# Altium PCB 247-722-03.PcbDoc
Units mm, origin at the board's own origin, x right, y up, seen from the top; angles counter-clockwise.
Board outline 143.8 x 64 mm, 4 copper layers (Top Layer, Int1_T, Int2-B, Bottom (GND)), stack 1.57 mm thick; 113 components, 68 nets, 298 pads, 352 vias.
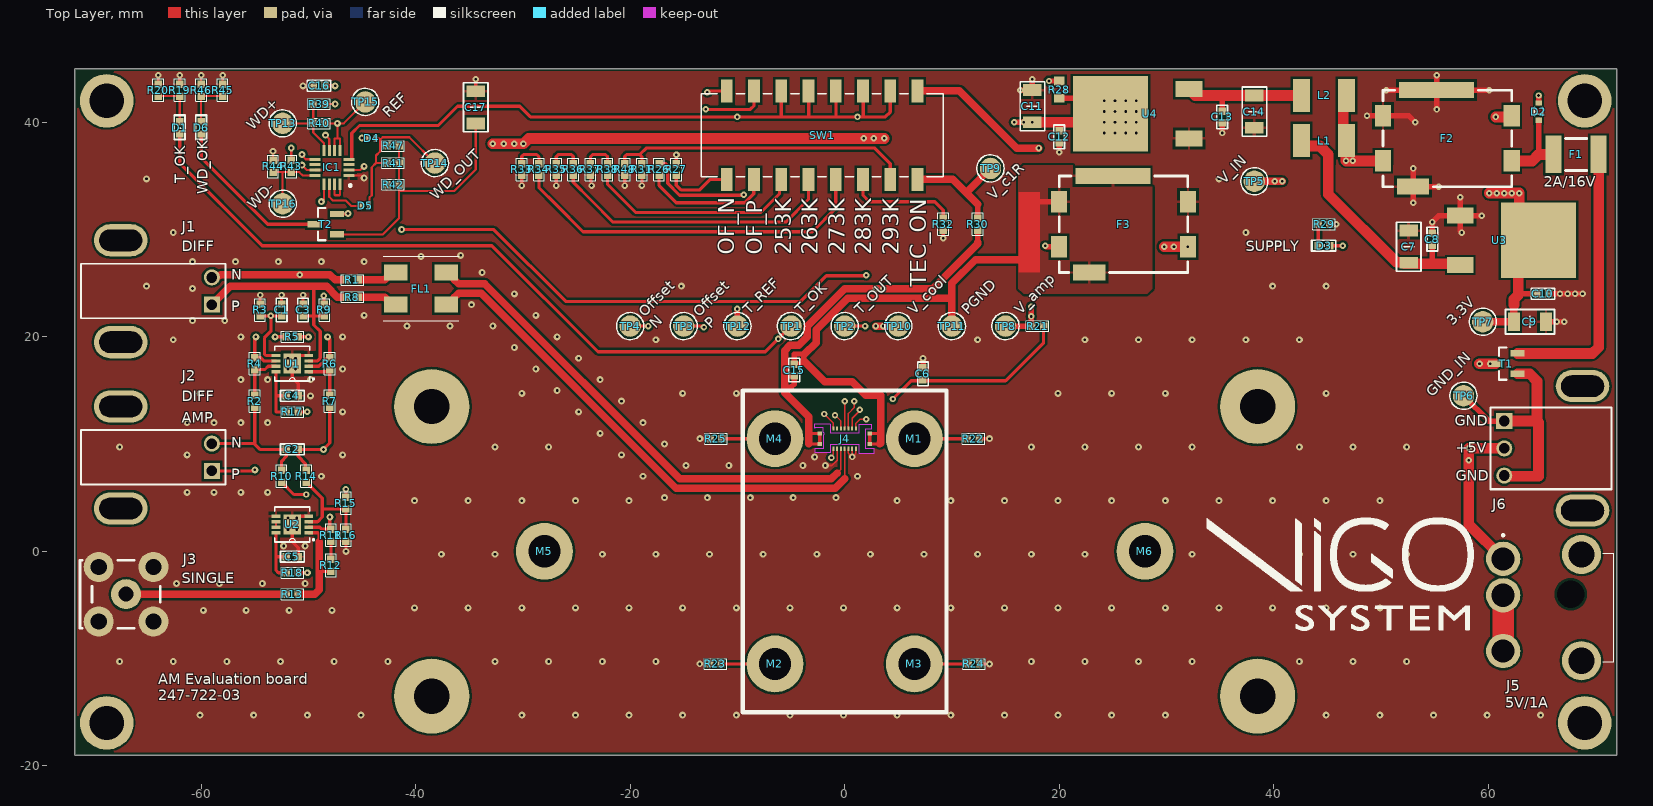
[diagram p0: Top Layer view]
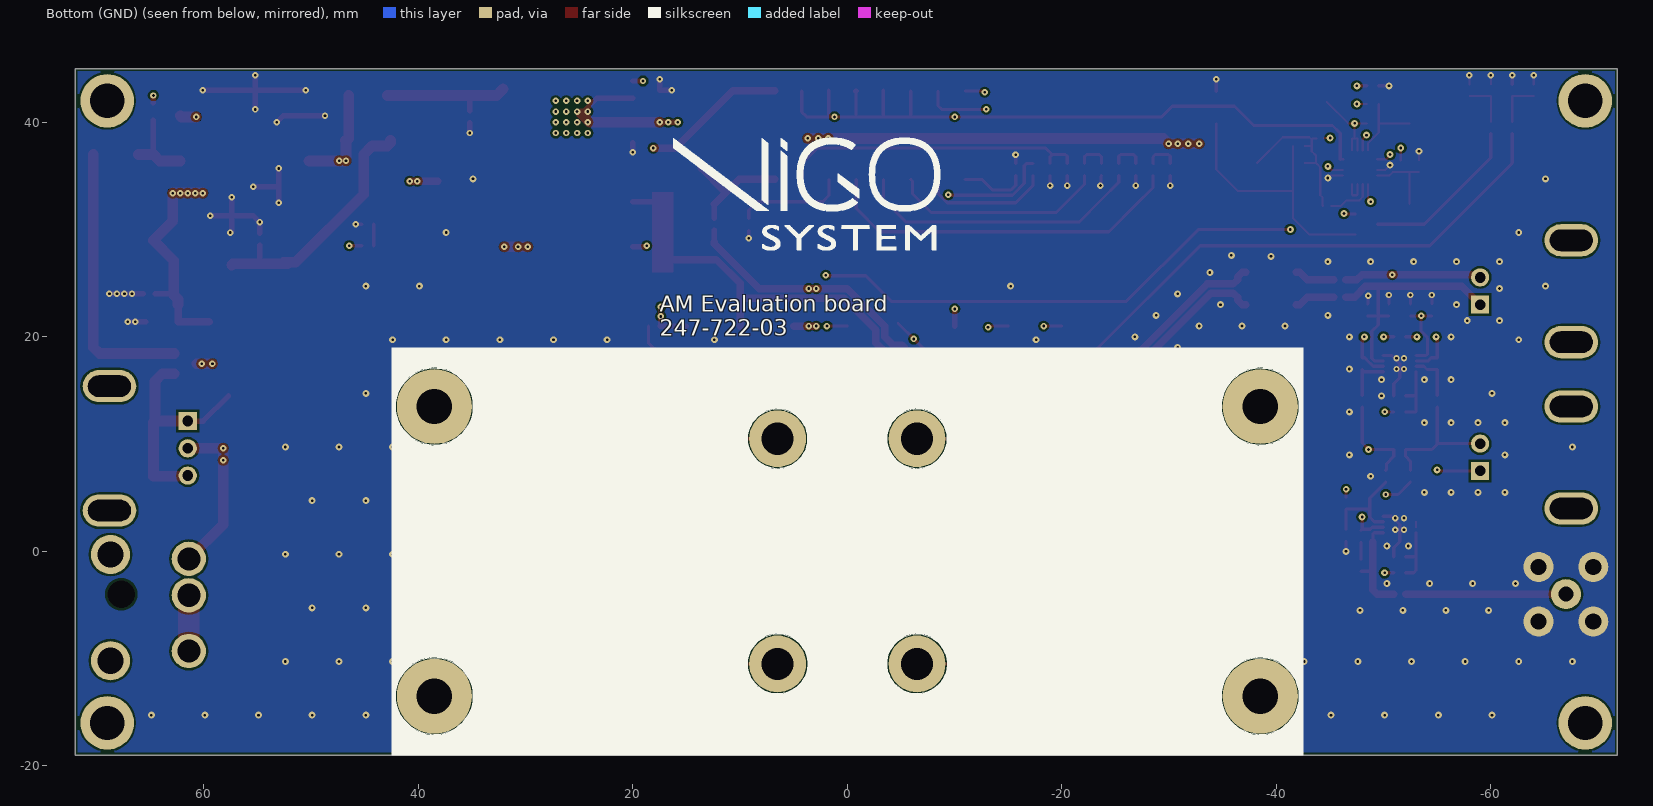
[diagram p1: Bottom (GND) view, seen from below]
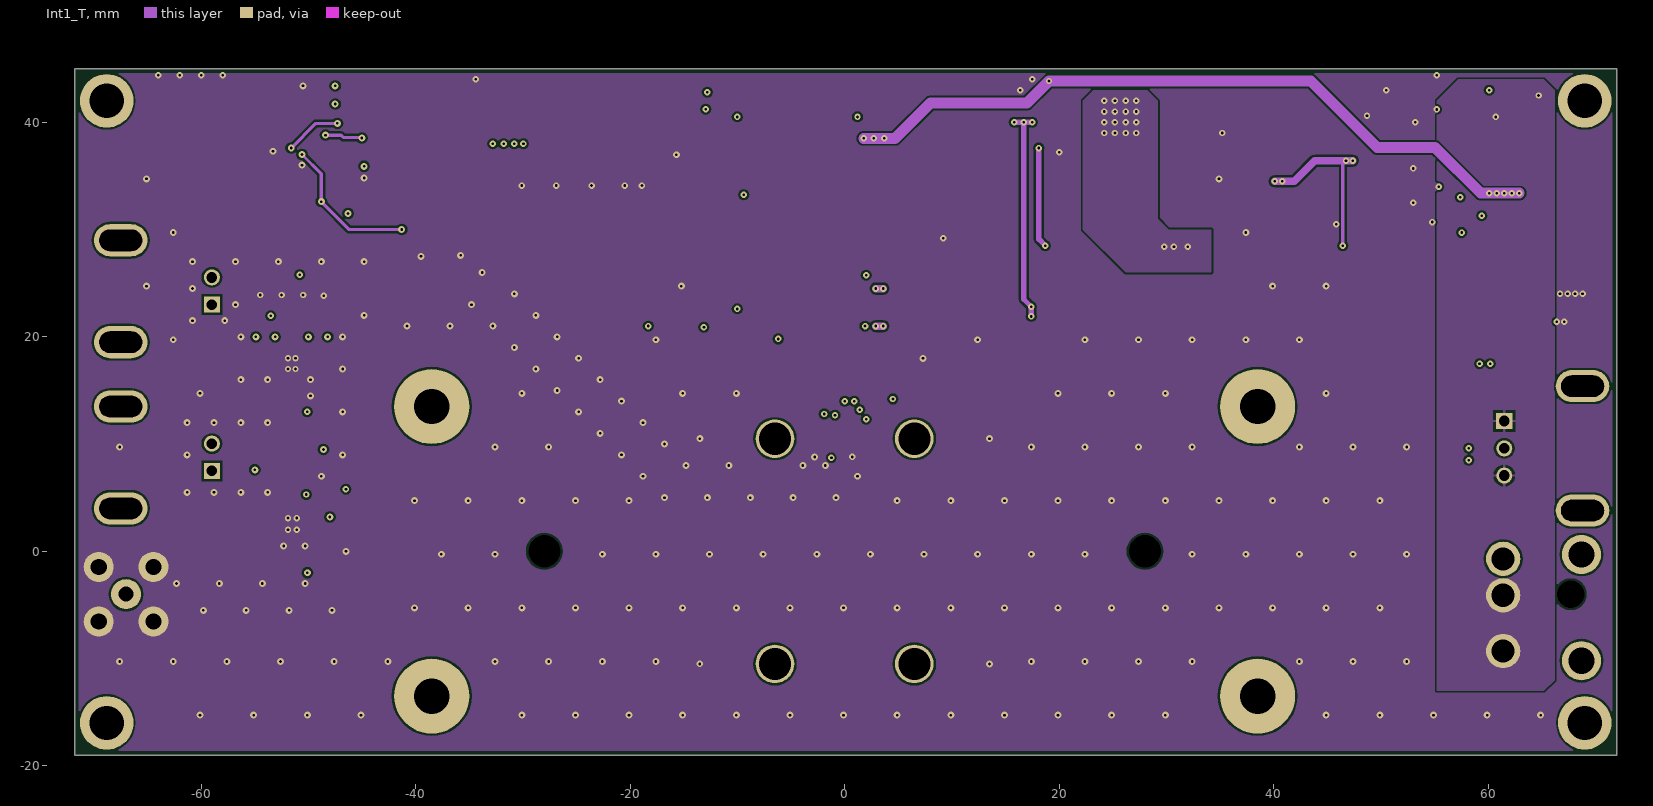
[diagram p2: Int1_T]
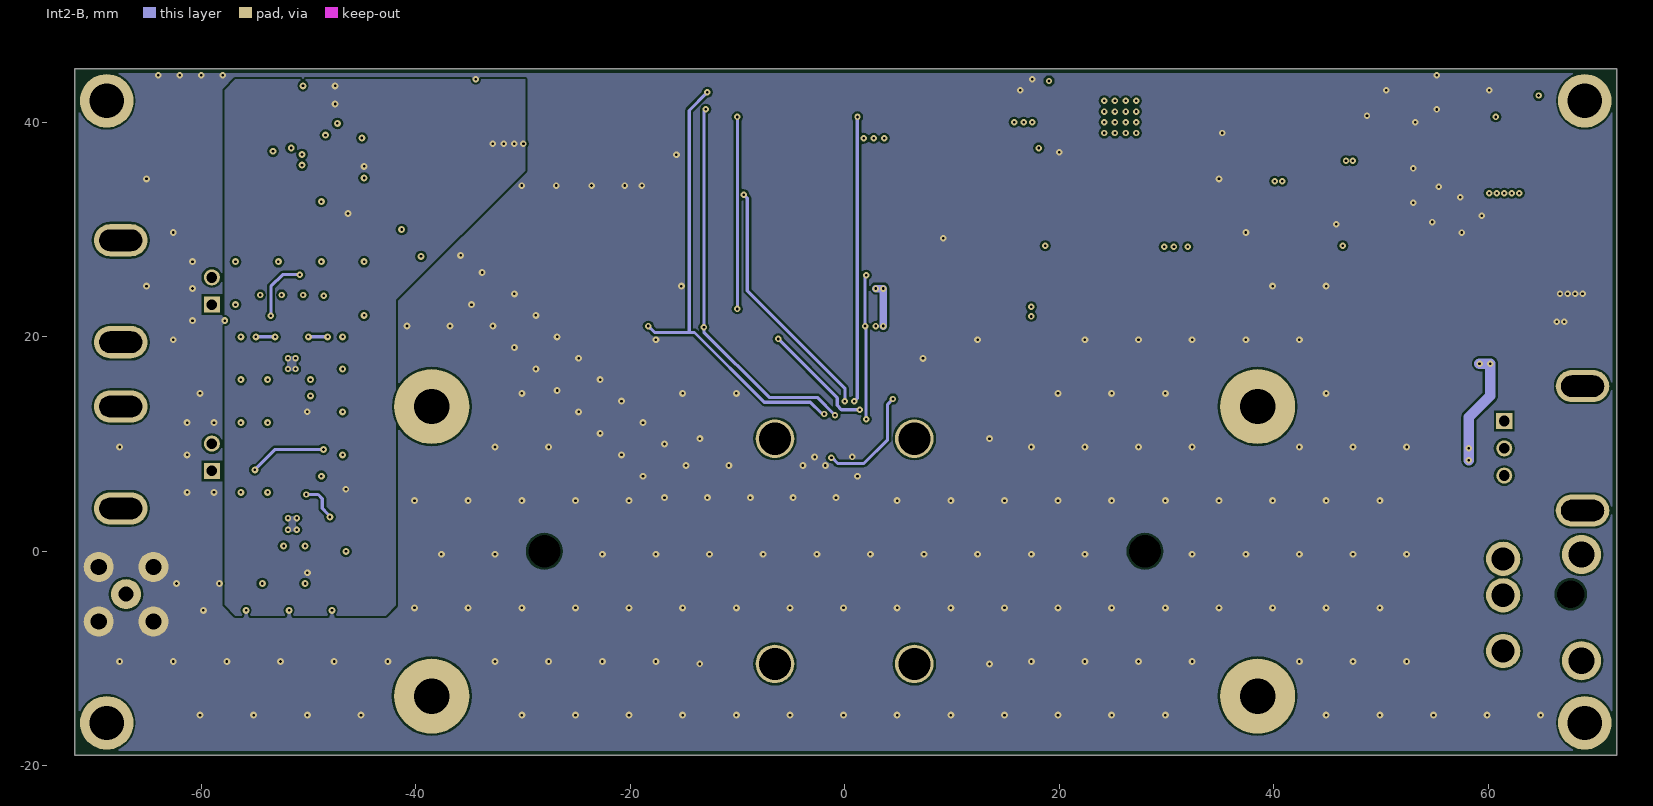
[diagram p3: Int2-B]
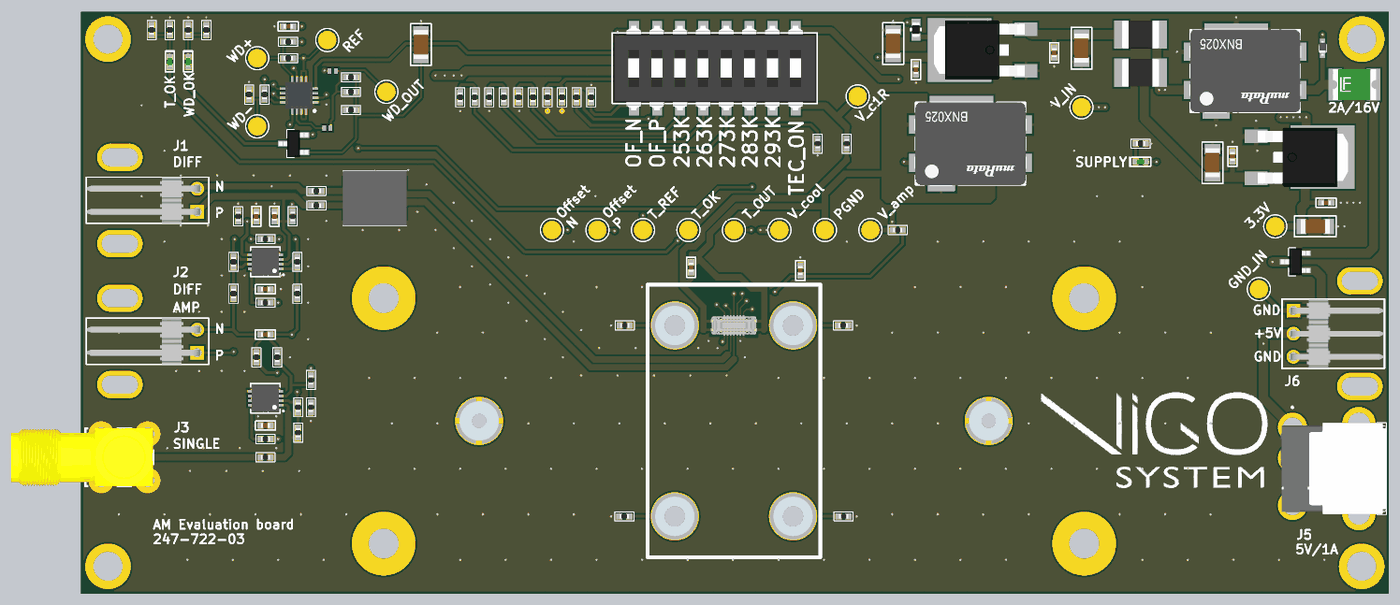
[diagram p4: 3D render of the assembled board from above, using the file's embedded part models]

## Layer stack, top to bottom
Top Solder: solder mask 0.025, SM-001, Dk 4
Top Layer: signal copper 0.035
Dielectric 1: core 0.36, Core-009, Dk 4.5
Int1_T: signal copper 0.035
Dielectric 6: prepreg 0.71, PP-006, Dk 4.1
Int2-B: signal copper 0.035
Dielectric 11: core 0.36, Core-009, Dk 4.5
Bottom (GND): signal copper 0.035
Bottom Solder: solder mask 0.025, SM-001, Dk 4

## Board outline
-71.8,-19 -71.8,45 72,45 72,-19

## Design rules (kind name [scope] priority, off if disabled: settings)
BoardOutlineClearance "BoardOutlineClearance inner layers" [(not IsKeepOut) and onMid] p1: gap=0.4 ignorepadtopadclearanceinfootprint=FALSE
BoardOutlineClearance "BoardOutlineClearance_1 outer layers" [(not IsKeepOut) and OnOutside] p2: gap=0.25 ignorepadtopadclearanceinfootprint=FALSE
Clearance Clearance_poly_50Ohm [InNetClass('50ohm')] p1: gap=0.3 ignorepadtopadclearanceinfootprint=FALSE except(0: Arc-Hole Track-Hole SMDPad-Hole THPad-Hole Via-Hole Fill-Hole Poly-Hole Region-Hole Text-Hole)
Clearance [not IsKeepOut vs not IsKeepOut] p2: gap=0.15 ignorepadtopadclearanceinfootprint=FALSE except(0: Arc-Hole Track-Hole SMDPad-Hole THPad-Hole Via-Hole Fill-Hole Poly-Hole Region-Hole Text-Hole; 0.2: Arc-Poly Track-Poly SMDPad-Poly THPad-Poly Via-Poly Fill-Poly Poly-Poly)
Clearance Clearance_keepout [All] p3: gap=0.001 ignorepadtopadclearanceinfootprint=FALSE except(0: Arc-Hole Track-Hole SMDPad-Hole THPad-Hole Via-Hole Fill-Hole Poly-Hole Region-Hole Text-Hole)
ComponentClearance [All] p1: gap=0.25 collisioncheckmode=3 verticalgap=0.2 showdistances=FALSE
DiffPairsRouting [All] p1: maxlimit=0.15 minlimit=0.15 mostfreqgap=0.15 toplayer_minwidth=0.15 toplayer_maxwidth=0.7 toplayer_prefwidth=0.15 midlayer1_minwidth=0.15 midlayer1_maxwidth=0.7 midlayer1_prefwidth=0.15 midlayer4_minwidth=0.15 midlayer4_maxwidth=0.7 midlayer4_prefwidth=0.15 bottomlayer_minwidth=0.15 bottomlayer_maxwidth=0.7 bottomlayer_prefwidth=0.15 maxuncoupledlength=12.5
Height [All] p1: minheight=0 maxheight=25 prefheight=12.5
HoleSize HoleSize-PTH [All] p1: absolutevalues=TRUE maxlimit=4 minlimit=0.25 maxpercent=80.000 minpercent=20.000
HoleToHoleClearance [All] p1: gap=0.35 allowstackedmicrovias=TRUE
MatchedLengths "Schematic Matched Net Lengths_1" [InNet('OUT_P')] p1: tolerance=2 checknetsindiffpair=TRUE checkdiffpairvsdiffpair=FALSE checkxsignals=FALSE checkothers=FALSE
MatchedLengths "Schematic Matched Net Lengths" [InNet('OUT_N')] p2: tolerance=2 checknetsindiffpair=TRUE checkdiffpairvsdiffpair=FALSE checkxsignals=FALSE checkothers=FALSE
MaxMinImpedance "Schematic Impedance Constraint_7" [InNet('OUTF_P')] p1: minimum=47,00 maximum=53,00
MaxMinImpedance "Schematic Impedance Constraint_6" [InNet('OUTF_N')] p2: minimum=47,00 maximum=53,00
MaxMinImpedance "Schematic Impedance Constraint_3" [InNet('NetR12_2')] p3: minimum=47,00 maximum=53,00
MaxMinImpedance "Schematic Impedance Constraint_2" [InNet('NetJ3_1')] p4: minimum=47,00 maximum=53,00
MinimumAnnularRing AR [All] p1: minimumring=0.174
MinimumSolderMaskSliver [All] p1: minsoldermaskwidth=0.08
PlaneClearance PlaneClearance-IPI [All] p1: clearance=0.25
PolygonConnect PolygonConnect-via [IsVia] p1: connectstyle=Direct reliefconductorwidth=0.254 reliefentries=4 polygonreliefangle="45 Angle" airgapwidth=0.254
PolygonConnect PolygonConnect-xTW_1_bottom [All vs OnLayer('Bottom Layer')] p2: connectstyle=Direct reliefconductorwidth=0.254 reliefentries=4 polygonreliefangle="90 Angle" airgapwidth=0.254
PolygonConnect PolygonConnect-xTW_1_bottom_1 [(PadIsPlated = 'False')] p3: connectstyle=Relief reliefconductorwidth=0.2 reliefentries=4 polygonreliefangle="90 Angle" airgapwidth=0.2
PolygonConnect PolygonConnect-big [AsMM(HoleDiameter) > 1] p4: connectstyle=Direct reliefconductorwidth=0.254 reliefentries=4 polygonreliefangle="90 Angle" airgapwidth=0.254
PolygonConnect PolygonConnect-xTW_1 [All] p5: connectstyle=Relief reliefconductorwidth=0.254 reliefentries=4 polygonreliefangle="90 Angle" airgapwidth=0.254
RoutingCorners [All] p1: cornerstyle=45-Degree minsetback=2.5 maxsetback=2.5
RoutingVias "RoutingVias > 0.45mm" [(ObjectKind = 'Via')] p1: holewidth=0.25 width=0.7 viastyle="Through Hole" minholewidth=0.25 minwidth=0.6 maxholewidth=0.9 maxwidth=1.25 // finishet hole size > 0.45mm
SilkToSilkClearance [All] p1: silktosilkclearance=0.2
SilkToSolderMaskClearance SilkscreenOverComponentPads [IsPad] p1: minsilkscreentomaskgap=0.04 clearancetoexposedcopper=TRUE
SolderMaskExpansion [All] p1: expansion=0
Width Width-xTW [not IsKeepOut] p1: maxlimit=2 minlimit=0.15 preferedwidth=0.7
20 further rules are at their usual default settings.

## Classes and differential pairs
component class "Window comparator": C16 C17 D4 D5 D6 IC1 R39 R40 R41 R42 R43 R44 R45 R46 R47 T2 TP13 TP14 TP15 TP16
component class TEMPERATURE: R31 R32 R33 R34 R35 R36 R37 R38 R48 TP12
component class SUP_MAIN: C7 C8 C9 C10 C11 C12 C13 C14 C15 D2 D3 F1 F2 F3 J5 J6 L1 L2 R28 R29 R30 T1 TP5 TP6 TP7 TP8 TP9 TP10 TP11 U3 U4
component class SUP_AMP: C4 C5 R17 R18
component class OFFSET: R26 R27 SW1 TP3 TP4
component class AMP: C1 C2 C3 J1 J2 J3 R1 R2 R3 R4 R5 R6 R7 R8 R9 R10 R11 R12 R13 R14 R15 R16 U1 U2
component class "247-722-03 Main": C6 D1 FL1 J4 M1 M2 M3 M4 M5 M6 R19 R20 R21 R22 R23 R24 R25 TP1 TP2
differential pair OUTF: +OUTF_P -OUTF_N
differential pair OUT: +OUT_P -OUT_N

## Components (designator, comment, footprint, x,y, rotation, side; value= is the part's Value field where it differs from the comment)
C1 "10p" 0402_CAP -52.5,22.5 r90 top
C2 "NC" 0402_CAP -51.5,9.5 r0 top
C3 "10p" 0402_CAP -50.5,22.5 r90 top
C4 "100n/35V" 0402_CAP -51.5,14.5 r0 top
C5 "100n/35V" 0402_CAP -51.5,-0.5 r0 top
C6 "100n/35V" 0402_CAP 7.3,16.55 r90 top
C7 "22u/25V" 1206_CAP_H 52.6,28.4 r270 top
C8 "100n/35V" 0402_CAP 54.8,29.1 r90 top
C9 "22u/25V" 1206_CAP_H 63.9,21.4 r180 top
C10 "100n/35V" 0402_CAP 65.1,24 r0 top
C11 "22u/25V" 1206_CAP_H 17.5,41.5 r270 top
C12 "100n/35V" 0402_CAP 20,38.65 r270 top
C13 "100n/35V" 0402_CAP 35.2,40.5 r270 top
C14 "22u/25V" 1206_CAP_H 38.2,41 r90 top
C15 "100n/35V" 0402_CAP -4.7,16.9 r90 top
C16 "100n/35V" 0402_CAP -49,43.4 r180 top
C17 "22u/25V" 1206_CAP_H -34.4,41.4 r270 top
D1 "T_OK" 0402_LED_G -62,39.5 r90 top value=KPG-1005VGC-TT
D2 "ESDA12-1K" SOD523 64.7,41 r270 top
D3 "SUPPLY" 0402_LED_G 44.7,28.5 r180 top value=KPG-1005VGC-TT
D4 "1PS10SB82" DFN-1006-2 -44.1,38.5 r0 top
D5 "1PS10SB82" DFN-1006-2 -44.7,32.2 r0 top
D6 "WD_OK" 0402_LED_G -60,39.5 r90 top value=KPG-1005VGC-TT
F1 "2.6A/16V" 1812_FUSE 68.2,37 r180 top
F2 "BNX025H01L" BNX025 57.2,38.5 r180 top
F3 "BNX025H01L" BNX025 27,30.5 r180 top
FL1 "PA4339.132NLT" PA4339132NLT -39.5,24.5 r0 top
IC1 "TSX564IQ4T" QFN16 -47.8,35.8 r180 top
J1 "10129379-902004BLF" HDR_100mil_1x2M_RA -59,24.27 r90 top
J2 "10129379-902004BLF" HDR_100mil_1x2M_RA -59,8.77 r90 top
J3 "3-1478978-1" "SMA_ 3-1478978-1" -67,-4 r180 top
J4 "101R014FB110" 101R014FB110 0,10.5 r0 top locked
J5 "2.5x5.5mm" PJ079BH 61.4,-0.7 r180 top value=PJ079BH
J6 "68016-403HLF" HDR_100mil_1x3M_RA 61.5,12.14 r270 top
L1 "56R@10MHz 10A" 1612_EMI 44.7,38.3 r180 top
L2 "56R@10MHz 10A" 1612_EMI 44.7,42.5 r180 top
M1 "9774010943R" TP_THT_1500_3000 6.5,10.5 r180 top locked
M2 "9774010943R" TP_THT_1500_3000 -6.5,-10.5 r180 top locked
M3 "9774010943R" TP_THT_1500_3000 6.5,-10.5 r180 top locked
M4 "9774010943R" TP_THT_1500_3000 -6.5,10.5 r180 top locked
M5 "9774025243R" 9774025243 -28,0 r0 top
M6 "9774025243R" 9774025243 28,0 r0 top
R1 "0R" 0402_RES -45.9,25.3 r0 top
R2 "0R" 0402_RES -55,14 r90 top
R3 "49R9" 0402_RES -54.5,22.5 r90 top
R4 "100R" 0402_RES -55,17.5 r90 top
R5 "49R9" 0402_RES -51.5,20 r0 top
R6 "100R" 0402_RES -48,17.5 r270 top
R7 "0R" 0402_RES -48,14 r90 top
R8 "0R" 0402_RES -45.9,23.7 r0 top
R9 "49R9" 0402_RES -48.5,22.5 r90 top
R10 "49R9" 0402_RES -52.5,7 r90 top
R11 "100R" 0402_RES -47.9,1.5 r90 top
R12 "100R" 0402_RES -47.9,-1.3 r90 top
R13 "49R9" 0402_RES -51.5,-4 r0 top
R14 "49R9" 0402_RES -50.2,7 r90 top
R15 "2.2k" 0402_RES -46.5,4.5 r90 top
R16 "220R" 0402_RES -46.5,1.5 r270 top
R17 "10R" 0402_RES -51.5,13 r180 top
R18 "10R" 0402_RES -51.5,-2 r180 top
R19 "2k" 0402_RES -62,43 r90 top
R20 "2k" 0402_RES -64,43 r90 top
R21 "0R" 0402_RES 18,21 r0 top
R22 "0R" 0402_RES 12,10.5 r0 top
R23 "0R" 0402_RES -12.05,-10.5 r180 top
R24 "0R" 0402_RES 12.05,-10.5 r0 top
R25 "0R" 0402_RES -12,10.5 r180 top
R26 "0R" 0402_RES -17.3,35.6 r270 top
R27 "0R" 0402_RES -15.7,35.6 r270 top
R28 "NC" 0603_RES 20,43.05 r270 top
R29 "2k" 0402_RES 44.7,30.5 r180 top
R30 "100m" 0402_RES 12.4,30.5 r90 top
R31 "4k7" 0402_RES -18.9,35.6 r270 top
R32 "4k7" 0402_RES 9.2,30.5 r270 top
R33 "390R" 0402_RES -30.1,35.6 r270 top
R34 "7k5" 0402_RES -28.5,35.6 r90 top
R35 "4k7" 0402_RES -26.9,35.6 r270 top
R36 "10k" 0402_RES -25.3,35.6 r90 top
R37 "2k" 0402_RES -23.7,35.6 r270 top
R38 "33k" 0402_RES -22.1,35.6 r90 top
R39 "10k" 0402_RES -49,41.7 r180 top
R40 "22R" 0402_RES -49,39.9 r0 top
R41 "2k" 0402_RES -42.1,36.2 r0 top
R42 "33k" 0402_RES -42.1,34.2 r0 top
R43 "22R" 0402_RES -51.6,35.9 r270 top
R44 "10k" 0402_RES -53.3,35.9 r270 top
R45 "2k" 0402_RES -58,43 r270 top
R46 "2k" 0402_RES -60,43 r270 top
R47 "2k" 0402_RES -42.1,37.8 r0 top
R48 "7k5" 0402_RES -20.5,35.6 r270 top
SW1 "A6SN-8104-P" SW_A6SN-8101_OMR -2.1,38.8 r90 top
T1 "Si2319CDS" SOT23-GSD 61.7,17.5 r180 top
T2 "Si2319CDS" SOT23-GSD -48.4,30.5 r180 top
TP1 "T_OK" TP_2 -5,21 r180 top
TP2 "=Value" TP_2 0,21 r270 top
TP3 "OffsetP" TP_2 -15,21 r0 top
TP4 "OffsetN" TP_2 -20,21 r90 top
TP5 "V_in" TP_2 38.2,34.5 r180 top
TP6 "Value" TP_2 57.7,14.5 r180 top
TP7 "3.3V" TP_2 59.5,21.4 r180 top
TP8 "V_amp" TP_2 15,21 r180 top
TP9 "V_c1R" TP_2 13.6,35.7 r180 top
TP10 "V_cool" TP_2 5,21 r180 top
TP11 "Value" TP_2 10,21 r180 top
TP12 "T_REF" TP_2 -10,21 r270 top
TP13 "WD+" TP_2 -52.4,39.9 r270 top
TP14 "WD_OUT" TP_2 -38.2,36.2 r270 top
TP15 "REF" TP_2 -44.7,41.9 r270 top
TP16 "WD-" TP_2 -52.4,32.4 r270 top
U1 "ADA4896-2ACPZ" LFCSP-8 -51.5,17.5 r180 top
U2 "ADA4896-2ACPZ" LFCSP-8 -51.5,2.5 r180 top
U3 "3V3" TO252 62.3,29 r0 top value=AZ1084CD-3.3TRG1
U4 "3V3" TO252 27.2,40.8 r180 top value=AZ1084CD-3.3TRG1

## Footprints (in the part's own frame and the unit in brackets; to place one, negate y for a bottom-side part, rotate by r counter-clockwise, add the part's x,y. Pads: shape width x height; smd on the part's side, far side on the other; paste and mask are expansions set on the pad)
101R014FB110 [mm] "14pins + 2 power paths"
  rect 0.18x0.4 smd: 1(-1.05,-0.95) 2(-1.05,0.95) 3(-0.7,-0.95) 4(-0.7,0.95) 5(-0.35,-0.95) 6(-0.35,0.95) 7(0,-0.95) 8(0,0.95) 9(0.35,-0.95) 10(0.35,0.95) 11(0.7,-0.95) 12(0.7,0.95) 13(1.05,-0.95) 14(1.05,0.95)
  rect 0.4x0.385 smd: MP1(-2.33,-0.483) MP2(-2.33,0.483) MP3(2.33,-0.483) MP4(2.33,0.483)
  body extent -2.45,-0.99 2.45,1.01, height 0.78
0402_CAP [mm]
  rect 0.7x0.7 smd paste-0.03: 1(0.55,0) 2(-0.55,0)
  silkscreen extent -1.1,-0.5 1.1,0.5, body extent -0.5,-0.25 0.5,0.25, height 0.5
0402_LED_G [mm]
  rect 0.7x0.7 smd paste-0.03 mask+0.03: 1(-0.55,0) 2(0.55,0)
  silkscreen extent -1.1,-0.5 1.2,0.5, body extent -0.5,-0.25 0.51,0.25, height 0.45
0402_RES [mm]
  rect 0.7x0.7 smd paste-0.03: 1(0.55,0) 2(-0.55,0)
  silkscreen extent -1.05,-0.5 1.05,0.5, body extent -0.5,-0.25 0.5,0.25, height 0.3
0603_RES [mm]
  rect 0.8x1 smd: 1(-0.8,0) 2(0.8,0)
  silkscreen extent -0.1,-0.55 0.1,0.55, body extent -0.81,-0.41 0.81,0.41, height 0.81
1206_CAP_H [mm]
  rect 1.1x1.7 smd: 1(-1.499,0) 2(1.499,0)
  silkscreen extent -2.29,-1.14 2.29,1.14, body extent -1.6,-0.8 1.6,0.8, height 1.6
1612_EMI [mm] "3216(metric)"
  rect 1.6x3.1 smd: 1(-2.1,0) 2(2.1,0)
  body extent -2.03,-1.52 2.03,1.53, height 2.28
1812_FUSE [mm]
  rect 1.5x3.5 smd: 1(-2.1,0) 2(2.1,0)
  silkscreen extent -1,-1.5 1,1.5, body extent -2.37,-1.71 2.36,1.7, height 1.34
9774025243 [mm] "SMT Steel Spacer with internal Thread M2, height 2.5mm"
  round 5.3 / inner round 0 / far side round 0 hole 3 unplated: 1(0,0)
  body extent -2.17,-2.17 2.18,2.17, height 2.5
BNX025 [mm] "Murata filter"
  rect 1.5x2 smd: 1(-5,2.1) 2(7,2.1) 3(-5,-2.1) 4(7,-2.1)
  rect 7x1.5 smd: 4(2,-4.5)
  rect 3x1.5 smd: 4(4.2,4.5)
  silkscreen extent -5,-4.5 7,4.5, body extent -5.15,-4.65 7.15,4.65, height 3.5
DFN-1006-2 [mm]
  rect 0.4x0.6 smd: 1(-0.35,0) 2(0.35,0)
HDR_100mil_1x2M_RA [mm]
  rect 1.5x1.5 / inner rect 1.5x1.5 / far side rect 1.7x1.7 hole 1: 1(-1.27,0)
  round 1.5 / inner round 1.5 / far side round 1.7 hole 1: 2(1.27,0)
  silkscreen extent -2.54,-1.27 2.54,12.2, body extent -2.54,-0.3 2.54,12.16, height 2.42
HDR_100mil_1x3M_RA [mm] "Connector; Header; 3 Position"
  rect 1.5x1.5 / inner rect 1.5x1.5 / far side rect 1.7x1.7 hole 1: 1(0,0)
  round 1.5 / inner round 1.5 / far side round 1.7 hole 1: 2(2.54,0) 3(5.08,0)
  silkscreen extent -1.27,-1.27 6.35,10, body extent -1.26,-0.33 6.36,9.87, height 2.42
LFCSP-8 [mil]
  rect 32x12 smd mask+1.97: 1(-60,30) 2(-60,10) 3(-60,-10) 4(-60,-30) 5(60,-30) 6(60,-10) 7(60,10) 8(60,30)
  rect 63x74 smd mask+1.97: 9(0,0)
  silkscreen extent -79,-64 64,64, body extent -59,-59 59,59, height 31
PA4339132NLT [mm]
  rect 2.2x1.5 smd: 1(-2.35,1.5) 2(-2.35,-1.5) 3(2.35,-1.5) 4(2.35,1.5)
  silkscreen extent -3.5,-3 3.5,3, body extent -3.5,-3 3.5,3, height 3.9
PJ079BH [mm]
  round 3.2 hole 2.154: 1(0,0) 2(0,8.6) 3(0,3.4)
  round 3.653 hole 2.435: MH1(-7.3,9.5) MH2(-7.3,-0.4)
  round 1.3 hole 2.6 unplated: MH3(-6.3,3.3)
  silkscreen extent -10.3,-2.3 0.1,9.6, body extent -10.32,-0.49 1.33,9.58, height 7.29
QFN16 [mm]
  rect 1.05x0.28 smd paste-0.025 mask+0.04: 1(-1.575,0.75) 2(-1.575,0.25) 3(-1.575,-0.25) 4(-1.575,-0.75) 9(1.575,-0.75) 10(1.575,-0.25) 11(1.575,0.25) 12(1.575,0.75)
  rect 0.28x1.05 smd paste-0.025 mask+0.04: 5(-0.75,-1.575) 6(-0.25,-1.575) 7(0.25,-1.575) 8(0.75,-1.575) 13(0.75,1.575) 14(0.25,1.575) 15(-0.25,1.575) 16(-0.75,1.575)
  silkscreen extent -1.8,1.6 -1.6,1.8, body extent -1.52,-1.52 1.52,1.52, height 0.9
"SMA_ 3-1478978-1" [mm]
  round 2.8 hole 1.4: 1(0,0)
  round 2.8 hole 1.5: 2(-2.55,2.55) 2(-2.55,-2.55) 2(2.55,2.55) 2(2.55,-2.55)
  silkscreen extent -3.17,-3.17 4.3,3.18, body extent -3.13,-3.17 12.42,3.18, height 10.11
SOD523 [mm]
  rect 0.5x0.6 smd: 1(-0.8,0) 2(0.8,0)
  silkscreen extent -0.38,-0.38 0.38,0.38, body extent -0.8,-0.4 0.8,0.4, height 0.7
SOT23-GSD [mm]
  rect 1.3x0.6 smd: 1(-1.05,0.95) 2(1.05,0) 3(-1.05,-0.95)
  silkscreen extent 0,-1.5 0.7,1.5, body extent -1.6,-1.5 1.6,1.5, height 1.1
SW_A6SN-8101_OMR [mm]
  rect 2.15x1.1 smd paste+0 mask+0: 1(-4.125,8.89) 2(-4.125,6.35) 3(-4.125,3.81) 4(-4.125,1.27) 5(-4.125,-1.27) 6(-4.125,-3.81) 7(-4.125,-6.35) 8(-4.125,-8.89) 9(4.125,-8.89) 10(4.125,-6.35) 11(4.125,-3.81) 12(4.125,-1.27) 13(4.125,1.27) 14(4.125,3.81) 15(4.125,6.35) 16(4.125,8.89)
  silkscreen extent -3.88,-11.28 3.88,11.28, body extent -4.65,-11.15 4.65,11.15, height 4.56
TO252 [mm] "D-PAK, 3-Pads, Body 5,8x6,7mm (max), IPC Low Density"
  rect 2.5x1.5 smd: 1(-4.9,2.3) 3(-4.9,-2.3)
  rect 7x7 smd: 2(2.4,0)
  body extent -4.74,-3.25 5.2,3.25, height 2.2
TP_2 [mm] "Test Point"
  round 2 smd paste-1: 1(0,0)
  silkscreen extent -1.27,-1.27 1.27,1.27
TP_THT_1500_3000 [mm]
  round 5.3 / inner round 3.6 / far side round 5.3 hole 3: 1(0,0)
  body extent -2.17,-2.17 2.18,2.17, height 1.01

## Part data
C1 C3: library part cap_0402_10p, "Ceramic capacitor", Supplier Part Number 1=CL05C100CB5NNNC
C2: library part cap_0402_4p7_50V, "Ceramic capacitor", Supplier Part Number 1=CL05C4R7BB5NNNC
C4 C5 C6 C8 C10 C12 C13 C15 C16: library part cap_0402_100n_35V, "Ceramic capacitor", Manufacturer="Taiyo Yuden", Supplier Part Number 1=2113067
C7 C9 C11 C14 C17: library part cap_1206_22u_25V, "Ceramic capacitor", Supplier Part Number 1=1797010
D1 D3 D6: library part d_LED_0402_G, Manufacturer=Kinbright, Supplier Part Number 1=KPG-1005CGC-TT
D2: library part d_TVS_ESDA12-1K, Manufacturer="Diodes Incorporated"
D4 D5: library part d_1PS10SB82, "Schottky barrier diode, low capacitance (1pF)", Manufacturer=Nexperia
F1: library part f_PTC_1812_2A6_16V, Supplier Part Number 1=650-MINISMDC260F/162
F2 F3: library part fil_BNX025H01L, Manufacturer=Murata
FL1: library part b_PA4339.132NLT, "Filter", Manufacturer=Pulse, Mouser Part Number=673-PA4339.132NLT
IC1: library part ic_TSX564IQ4T, "quad rail-to-rail precision opamp", Manufacturer=ST, Supplier Part Number 1=497-13695-1-ND
J1 J2: library part j_HDR_100mil_1x2_RA, "Header, 2-Pin", Manufacturer=Amphenol, Supplier Part Number 1=649-1012937990204BLF
J3: library part j_SMA_3-1478978-1, Manufacturer="TE Connectivity"
J4: library part j_101R014FB110, "14pin + 2 power paths, 0.35mm pitch", Manufacturer="Amphenol ICC", Manufacturer_Name="Amphenol ICC / Aorora", Supplier Part Number 1=3577436
J5: library part j_PJ-079BH, "Connector", Arrow Part Number=PJ-079BH, Manufacturer="CUI Devices", Manufacturer_Name="CUI Inc.", Mouser Part Number=490-PJ-079BH
J6: library part j_HDR_100mil_1x3_RA, "Header, 3-Pin", Manufacturer=Amphenol, Supplier Part Number 1=649-68016-403HLF
L1 L2: library part l_1612_EMI_56R_10A, "DO5040H-103", Supplier Part Number 1=875-DM1612X560R-10
M1 M2 M3 M4: library part m_spacer_1mm_fi2.25_WA-SMST_9774010943, Manufacturer="Wurth Elektronik", Supplier Part Number 1=732-10938-1-ND
M5 M6: library part m_spacer_2.5mm_fi2.25_WA_SMT_9774025243, "WA-SMSI SMT Steel Spacer, internal Thread, OD 4.35mm, M2x2.5mm", Manufacturer="Wurth Elektronik", Manufacturer Part Number=9774025243, Operating Temperature="-55 to +150degC"
R1 R2 R7 R8 R21 R22 R23 R24 R25 R26 R27: library part res_0402_0R, "Resistior", Supplier Part Number 1=SMD0402-0R
R3 R5 R9 R10 R13 R14: library part res_49R9/0.1%/TF, "Resistior", Manufacturer=Yageo
R4 R6 R11 R12: library part res_0402_100R/0.1%/TF, "Resistior", Manufacturer=Yageo, Supplier Part Number 1=YAG2301CT-ND
R15: library part res_0402_2.2k/0.1%/TF, "Resistior", Manufacturer=Yageo, Supplier Part Number 1=YAG1402CT-ND
R16: library part res_0402_220R/0.1%/TF, "Resistior", Manufacturer=Yageo, Supplier Part Number 1=YAG4207CT-ND
R17 R18: library part res_0402_10R, "Resistior", Supplier Part Number 1=SMD0402-10R-1%
R19 R20 R29 R37 R41 R45 R46 R47: library part res_0402_2k, "Resistior", Supplier Part Number 1=SMD0402-2k-1%
R28: library part res_0603_NC, "Resistior"
R30: library part res_0402_0R10, "Resistior", Manufacturer=YAGEO, Supplier Part Number 1=603-RL0402FR070R1L
R31 R32 R35: library part res_0402_4k7, "Resistior", Supplier Part Number 1=SMD0402-4k7-1%
R33: library part res_0402_390R, "Resistior", Supplier Part Number 1=SMD0402-390R-1%
R34 R48: library part res_0402_7k5, "Resistior", Supplier Part Number 1=SMD0402-7k5-1%
R36 R39 R44: library part res_0402_10k, "Resistior", Supplier Part Number 1=SMD0402-10K
R38 R42: library part res_0402_33k, "Resistior", Supplier Part Number 1=SMD0402-33k-1%
R40 R43: library part res_0402_22R, "Resistior", Supplier Part Number 1=SMD0402-22R-1%
SW1: library part s_DIP_8_S, "No Description Available", Manufacturer=Omron, Manufacturer_Part_Number=A6SN-8101, Supplier Part Number 1=653-A6SN-8104-P
T1 T2: library part t_Si2319CDS, Manufacturer=Vishay, Supplier Part Number 1=SI2319CDS-T1-GE3
TP1 TP2 TP3 TP4 TP5 TP6 TP7 TP8 TP9 TP10 TP11 TP12 TP13 TP14 TP15 TP16: library part m_TP_2, "Test Point"
U1 U2: library part ic_ADA4896-2, "opamp", Manufacturer="Analog Devices"
U3 U4: library part ic_AZ1084CD-3.3TRG1, "3-TERMINAL  LDO", Manufacturer="DIODES Incorporated", Supplier Part Number 1=AZ1084CD-3.3TRG1DITR-ND

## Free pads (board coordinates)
  round 7 hole 3.3: 49(-38.5,-13.5) 49(-38.5,13.5) 49(38.5,-13.5) 49(38.5,13.5)
  oval 5x3 hole 2 slot 4 at 0 deg: 50(-67.5,29) 50(68.8,15.4) 51(-67.5,19.5) 51(68.8,3.8) 52(-67.5,13.5) 53(-67.5,4)
  round 5 hole 3.2: 54(-68.8,42) 55(-68.8,-16) 56(69,-16) 57(69,42)

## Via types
v1: diameter 0.65, hole 0.25, Top Layer to Bottom (GND), tented both sides, 225 vias
v2: diameter 0.6, hole 0.25, Top Layer to Bottom (GND), tented both sides, 125 vias
v3: diameter 0.6, hole 0.25, Top Layer to Bottom (GND), 2 vias

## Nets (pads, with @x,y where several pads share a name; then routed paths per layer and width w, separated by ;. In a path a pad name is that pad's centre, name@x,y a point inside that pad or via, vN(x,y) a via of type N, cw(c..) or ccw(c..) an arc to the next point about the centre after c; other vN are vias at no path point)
3V3: C9.2 C10.2 C16.2 IC1.2 R15.1 R17.2 R18.2 R28.1 R39.2 T2.3 TP7.1 U3.2 | length 133.7
  Top Layer w0.2: R39.2 v1(-47.5,41.7) ; v1@-46.35,31.45 v1(-46.3,31.5) ; IC1.2 -45.15,35.55 v1(-44.8,35.9)
  Top Layer w0.3: R18.2 -50,-2 v1(-50.1,-2) ; R17.2 v2(-50.1,13) ; C16.2 v1(-47.5,43.4) ; T2.3 v1@-46.35,31.45 ; R15.1 v2(-46.5,5.8)
  Top Layer w0.5: v2(19.05,43.85) R28.1 ; 62.8,23.9 62.9,24 C10.2
  Top Layer w0.7: TP7.1 C9.2 62.4,21.401 62.4,23
  Top Layer w1: v2(-32.8,38) v2(-31.8,38) v2(-30.8,38) v2(-29.95,38) -29.45,38.5 v2(1.778,38.5) v2(2.7,38.5) v2(3.7,38.5) ; v2(60.1,33.4) v2(60.8,33.4) v2(61.5,33.4) v2(62.2,33.4) v2(62.9,33.4) 62.9,30.8 U3.2 62.8,27.1 62.8,23.9 62.4,23.5 62.4,23
  Int1_T w1: v2(1.778,38.5) v2(2.7,38.5) v2(3.7,38.5) 4.7,38.5 8,41.8 17,41.8 v2(19.05,43.85) 43.45,43.85 49.65,37.65 55.05,37.65 59.3,33.4 v2(60.1,33.4) v2(60.8,33.4) v2(61.5,33.4) v2(62.2,33.4) v2(62.9,33.4)
GND: C1.1 C3.1 C4.1 C5.1 C6.1 C7.1 C8.1 C9.1 C10.1 C11.1 C12.1 C13.1 C14.1 C16.1 C17.1 F2.4 F3.3 IC1.1 IC1.11 J3.2 J4.3 J4.9 J4.11 J4.13 R3.1 R9.1 R16.1 R19.1 R20.1 R22.1 R23.1 R24.1 R25.1 R27.2 R29.2 R31.1 R32.1 R33.1 R35.1 R37.1 R42.2 R44.2 R45.2 R46.2 R48.1 U1.4 U1.9 U2.4 U2.5 U2.9 U3.1 U4.1 | length 81.3
  Top Layer w0.15: v1(-1.8,8) -1.2,8 -0.7,8.5 J4.3 ; J4.9 0.35,9.15 v2(0.7,8.8) ; J4.11 v2(0.7,8.8) ; J4.13 1.05,9.15 v2(0.7,8.8)
  Top Layer w0.2: R20.1 v2(-64,44.4) ; R46.2 v2(-60,44.4) ; R45.2 v2(-58,44.4) ; R44.2 v1(-53.3,37.3) ; v1(-50.6,36) -50.15,35.55 IC1.11 ; IC1.1 -45.05,35.05 v1(-44.8,34.8)
  Top Layer w0.3: R19.1 v2(-62,44.4) ; R3.1 v2(-54.5,23.9) ; C1.1 v2(-52.5,23.9) ; C5.1 -50.95,0.35 -51.5,0.9 U2.9 -50.738,3.262 U2.4 ; C4.1 -50.95,15.629 -51.5,16.179 U1.9 -50.738,18.262 U1.4 ; C3.1 v2(-50.5,23.9) ; v1(-50.5,43.4) C16.1 ; v2(-48.566,23.834) -48.533,23.801 -48.533,23.083 R9.1 ; v1(-46.5,0) R16.1 ; C17.1 v2(-34.4,44) ; v2(-30.1,34.1) R33.1 ; v2(-26.9,34.1) R35.1 ; R37.1 -23.65,35 -23.65,34.15 v2(-23.6,34.1) ; v3(-20.5,34.1) R48.1 ; v3(-18.9,34.1) R31.1 ; R27.2 v1(-15.7,36.975) ; v2(-13.5,-10.5) R23.1 ; v1(-13.5,10.5) R25.1 ; v2(9.2,29.2) R32.1@9.2,29.9 ; R22.1 v1(13.5,10.5) ; R24.1 v1(13.5,-10.5) ; R29.2 v2(45.85,30.5)
  Top Layer w0.5: C6.1 7.317,17.117 7.317,17.983 v1(7.308,17.992) ; v2(16.357,43) C11.1 C11.1 v2(17.5,44) ; v2(20,37.2) C12.1 ; v2(35.2,39) C13.1 ; v2(48.7,40.6) 50.2,40.6 52.6,40.6 v2(53.2,40) ; v2(50.5,43) F2.4@55.2,43 ; v2(53,32.5) F2.4@53,34 ; v2(53,35.7) F2.4@53,34 ; C8.1 v2(54.8,30.7) 55.4,31.3 U3.1 ; v2(55.2,41.2) F2.4@55.2,43 ; v2(55.2,44.4) F2.4@55.2,43 ; v2(55.4,34) F2.4@53,34 ; v2(57.4,33) U3.1 ; v2(57.522,29.722) 57.522,29.749 57.4,29.871 U3.1 ; v2(59.4,31.3) U3.1 ; v2(60.1,43) F2.4@55.2,43 ; C9.1 v2(67.1,21.4) ; C10.1 v2(66.7,24) v2(67.4,24) v2(68.1,24) v2(68.8,24)
  other v1: -60.1,-15.275 -55.1,-15.275 -50.1,-15.275 -45.1,-15.275 -30.1,-15.275 -25.1,-15.275 -20.1,-15.275 -15.1,-15.275 -10.1,-15.275 -5.1,-15.275 -0.1,-15.275 4.9,-15.275 9.9,-15.275 14.9,-15.275 19.9,-15.275 24.9,-15.275 29.9,-15.275 44.9,-15.275 49.9,-15.275 54.9,-15.275 59.9,-15.275 64.9,-15.275 -67.6,-10.275 -62.6,-10.275 -57.6,-10.275 -52.6,-10.275 -47.6,-10.275 -42.6,-10.275 -32.6,-10.275 -27.6,-10.275 -22.6,-10.275 -17.6,-10.275 17.4,-10.275 22.4,-10.275 27.4,-10.275 32.4,-10.275 42.4,-10.275 47.4,-10.275 52.4,-10.275 -59.8,-5.5 -55.8,-5.5 -51.8,-5.5 -47.8,-5.5 -40.1,-5.275 -35.1,-5.275 -30.1,-5.275 -25.1,-5.275 -20.1,-5.275 -15.1,-5.275 -10.1,-5.275 -5.1,-5.275 -0.1,-5.275 4.9,-5.275 9.9,-5.275 14.9,-5.275 19.9,-5.275 24.9,-5.275 29.9,-5.275 34.9,-5.275 39.9,-5.275 44.9,-5.275 49.9,-5.275 -62.3,-3 -58.3,-3 -54.3,-3 -50.3,-3 -37.6,-0.275 -32.6,-0.275 -22.6,-0.275 -17.6,-0.275 -12.6,-0.275 -7.6,-0.275 -2.6,-0.275 2.4,-0.275 7.4,-0.275 12.4,-0.275 17.4,-0.275 22.4,-0.275 32.4,-0.275 37.4,-0.275 42.4,-0.275 47.4,-0.275 52.4,-0.275 -52.3,0.5 -50.3,0.5 -40.1,4.725 -35.1,4.725 -30.1,4.725 -25.1,4.725 -20.1,4.725 4.9,4.725 9.9,4.725 14.9,4.725 19.9,4.725 24.9,4.725 29.9,4.725 34.9,4.725 39.9,4.725 44.9,4.725 49.9,4.725 -16.8,5 -12.8,5 -8.8,5 -4.8,5 -0.8,5 -61.3,5.5 -58.8,5.5 -56.3,5.5 -53.8,5.5 -48.8,7 -18.8,7 1.2,7 -14.8,8 -10.8,8 -3.9,8 -2.8,8.8 -61.3,9 -46.8,9 -20.8,9 -67.6,9.725 -32.6,9.725 -27.6,9.725 17.4,9.725 22.4,9.725 27.4,9.725 32.4,9.725 42.4,9.725 47.4,9.725 52.4,9.725 -16.8,10 -22.8,11 -61.3,12 -58.8,12 -56.3,12 -53.8,12 -18.8,12 -46.8,13 -24.8,13 -20.8,14 -49.8,14.5 -60.1,14.725 -30.1,14.725 -15.1,14.725 -10.1,14.725 19.9,14.725 24.9,14.725 29.9,14.725 44.9,14.725 -26.8,15 -56.3,16 -53.8,16 -49.8,16 -22.8,16 -46.8,17 -28.8,17 -24.8,18 -30.8,19 -62.6,19.725 -17.6,19.725 12.4,19.725 22.4,19.725 27.4,19.725 32.4,19.725 37.4,19.725 42.4,19.725 -56.3,20 -46.8,20 -26.8,20 -40.8,21 -36.8,21 -32.8,21 -60.8,21.5 -57.8,21.5 -44.8,22 -28.8,22 -56.8,23 -34.8,23 -30.8,24 -60.8,24.5 -65.1,24.725 -15.225,24.725 39.9,24.725 44.9,24.725 -33.8,26 -60.8,27 -56.8,27 -52.8,27 -48.8,27 -44.8,27 -39.5,27.5 -35.8,27.6 -62.6,29.725 37.4,29.725 -65.1,34.725 34.9,34.725
  other v2: -51.9,2 -51.1,2 -51.9,3.1 -51.1,3.1 -51.9,17 -51.2,17 -51.9,18 -51.2,18 66.4,21.4
NetC1_2: C1.2 J1.2 R1.2 R3.2 U1.5 | length 26
  Top Layer w0.3: J1.2 J1.2@-58.76,25.3 ; R3.2 v2(-53.5,21.95) ; U1.5 -53.962,18.262 -54.1,18.4 -54.1,19.9 -53.5,20.5 v2(-53.5,21.95) ; C1.2 v2(-53.5,21.95)
  Top Layer w0.7: J1.2 -58.847,25.693 -58.297,25.693 -58.19,25.8 v2(-50.8,25.8) -48,25.8 -47.5,25.3 R1.2
  Int2-B w0.3: v2(-53.5,21.95) -53.5,24.695 -52.395,25.8 v2(-50.8,25.8)
NetC2_1: C2.1 J2.1 R7.2 R14.1 | length 20
  Top Layer w0.3: J2.1 -55.1,7.5 v1(-55,7.6) ; R14.1 -50.274,7.624 -50.274,8.174 -50.95,8.85 C2.1 v1(-48.6,9.5) -48,10.1 R7.2
  Int2-B w0.3: v1(-55,7.6) -53.1,9.5 v1(-48.6,9.5)
NetC2_2: C2.2 J2.2 R2.2 R10.1 | length 12.7
  Top Layer w0.3: J2.2 -55.06,10.04 ; R2.2 -55,10.1 -55.06,10.04 ; R10.1 -52.5,8.4 -52.05,8.85 C2.2 -54.52,9.5 -55.06,10.04
NetC3_2: C3.2 J1.1 R8.2 R9.2 U1.3 | length 23.6
  Top Layer w0.3: C3.2 -49.5,21.95 ; U1.3 -49.146,17.754 -48.9,18 -48.9,20.5 -49.5,21.1 -49.5,21.95 ; -49.5,24.5 -49.5,21.95 ; R9.2 -49.5,21.95
  Top Layer w0.7: J1.1 -57.3,24.7 -48.3,24.7 -47.3,23.7 R8.2
NetC4_2: C4.2 R17.1 U1.8 | length 5.7
  Top Layer w0.3: U1.8 -53.024,14.524 ; R17.1 -53,13 -53.024,13.024 -53.024,14.524 ; C4.2 -53,14.5 -53.024,14.524
NetC5_2: C5.2 R18.1 U2.8 | length 5.6
  Top Layer w0.3: U2.8 -53.024,-0.5 ; R18.1 -52.8,-2 -53.024,-1.776 -53.024,-0.5 ; C5.2 -53.024,-0.5
NetC6_2: C6.2 J4.1 R21.1 | length 29.1
  Top Layer w0.15: v2(-1.234,8.709) -1.234,8.813 -1.05,8.997 J4.1
  Top Layer w0.3: v2(4.5,14.2) 6.207,15.907 15.007,15.907 18.55,19.45 R21.1
  Int2-B w0.3: v2(-1.234,8.709) -1.173,8.709 -0.664,8.2 1.8,8.2 4,10.4 4,13.7 v2(4.5,14.2)
NetC7_2: C7.2 C8.2 L1.2 U3.3 | length 24
  Top Layer w0.5: 54.75,26.8 54.8,26.85 C8.2
  Top Layer w1: L1.2 42.6,38.086 42.9,37.786 44.314,37.786 45.1,37 45.1,33.3 51.449,26.951 52.55,26.951 C7.2 ; C7.2@52.2,26.8 54.75,26.8 57.3,26.8 U3.3
NetC13_2: C13.2 C14.2 L2.2 U4.3 | length 12.5
  Top Layer w0.5: C13.2 35.2,42.5
  Top Layer w1: U4.3 32.7,42.5 35.2,42.5 L2.2@42.91,42.5
NetC17_2: C17.2 R41.1 R42.1 R47.1 T2.1 | length 25.5
  Top Layer w0.2: T2.1 -43.05,29.55 -41.55,31.05 -41.55,33.6 ; R47.1 R41.1 -41.55,33.6 ; C17.2 -34.4,35.6 -36.4,33.6 -41.55,33.6
NetD1_2: D1.2 R19.2 R20.2 | length 4.4
  Top Layer w0.2: R20.2 R19.2 D1.2
NetD2_1: D2.1 F2.3 J5.2 J5.3 J6.1 J6.3 T1.1 TP6.1 | length 29.5
  Top Layer w0.5: TP6.1 60.06,12.14 J6.1 ; D2.1 v2(64.7,42.5)
  Top Layer w1: v2(60.7,40.5) 62.1,40.5 F2.3 ; J6.3 61.56,7 64.7,7 64.7,12 64.56,12.14 ; J6.1 64.56,12.14 ; T1.1 63.87,16.55 64.56,15.86 64.56,12.14
  Top Layer w2: J5.2 J5.3
NetD2_2: D2.2 F1.2 F2.1 | length 7.3
  Top Layer w0.5: 64.7,37 D2.2
  Top Layer w1: F2.1 64.099,36.4 64.7,37 F1.2
NetD3_2: D3.2 R29.1 | length 2
  Top Layer w0.3: D3.2 R29.1
NetD4_1: D4.1 IC1.7 | length 5.7
  Top Layer w0.2: v1(-48.4,38.8) -48.05,38.45 IC1.7 ; v1@-45.031,38.551 v1(-45.016,38.537) -44.487,38.537 D4.1
  Int1_T w0.2: v1@-45.066,38.586 v1(-45.016,38.537)
  Int1_T w0.3: v1(-48.4,38.8) -46.95,38.8 -46.736,38.586 v1@-45.066,38.586
NetD4_2: D4.2 D5.2 R41.2 R47.2 TP14.1 | length 15
  Top Layer w0.2: D5.2 -44.3,32.25 -44.3,33 -44.1,33.2 -44.1,35.8 -43.7,36.2 ; D4.2 -43.417,38.5 -43.3,38.383 ; R41.2 -43.7,36.2 ; R47.2 -43.259,37.8 -43.3,37.841 ; TP14.1 -40.6,38.6 -43.083,38.6 -43.3,38.383 ; -43.7,36.2 -43.7,36.9 -43.3,37.3 -43.3,37.841 ; -43.3,37.841 -43.3,38.383
NetD5_1: D5.1 IC1.14 | length 4.5
  Top Layer w0.2: IC1.14 -48.05,33.05 -47.7,32.7 -46.5,32.7 -46,32.2 D5.1@-45.115,32.2
NetD6_1: D6.1 T2.2 | length 15.4
  Top Layer w0.3: D6.1 -60,36.7 -53.8,30.5 T2.2
NetD6_2: D6.2 R45.1 R46.1 | length 4.4
  Top Layer w0.2: D6.2 R46.1 R45.1
NetF1_1: F1.1 T1.3 | length 25.8
  Top Layer w1: T1.3 69.714,18.45 70.3,19.036 F1.1
NetF3_2: F3.2 SW1.9 | length 24.2
  Top Layer w0.5: v2(18.7,28.5) 18.8,28.4 F3.2
  Top Layer w0.7: SW1.9 6.815,42.95 10.7,42.95 16.05,37.6 v2(18.1,37.6)
  Int1_T w0.5: v2(18.1,37.6) 18.1,29.1 v2(18.7,28.5)
NetIC1_5: IC1.5 IC1.6 R40.1 R43.2 TP15.1 | length 15.1
  Top Layer w0.2: R43.2 v1(-51.6,37.6) ; R40.1 v1(-47.3,39.9) ; IC1.6 -47.55,38.5 -47.3,38.5 ; IC1.5 -47.05,38.45 -47.1,38.5 -47.3,38.5 ; TP15.1 -46.7,39.9 v1(-47.3,39.9) ; -47.3,38.5 v1(-47.3,39.9)
  Int1_T w0.3: v1(-51.6,37.6) -49.3,39.9 v1(-47.3,39.9)
NetIC1_8: IC1.8 R39.1 R40.2 TP13.1 | length 7.6
  Top Layer w0.2: TP13.1 R40.2 ; R39.1 R40.2 ; IC1.8 -48.55,38.05 -49.55,39.05 R40.2
NetIC1_12: IC1.12 R43.1 R44.1 TP16.1 | length 7
  Top Layer w0.2: R44.1 -52.45,35.35 ; TP16.1 -52.4,35.3 -52.45,35.35 ; IC1.12 -50.55,35.05 -50.85,35.35 R43.1 -52.45,35.35
NetIC1_15: IC1.15 IC1.16 | length 2.5
  Top Layer w0.2: IC1.15 -47.55,33.25 -47.5,33.2 -47.1,33.2 -47.05,33.25 IC1.16
NetJ3_1: J3.1 R13.2 | length 15
  Top Layer w0.7: J3.1 -60.3,-4 R13.2
NetJ5_1: J5.1 J6.2 T1.2 | length 27.2
  Top Layer w1: v2(59.2,17.5) v2(60.2,17.5) T1.2 ; J5.1 58.2,2.5 v2(58.2,8.5) v2(58.2,9.6) J6.2
  Int2-B w1: v2(58.2,8.5) v2(58.2,9.6) 58.2,12.5 60.2,14.5 v2(60.2,17.5) v2(59.2,17.5)
NetM1_1: M1.1 R22.2 | length 5
  Top Layer w0.3: M1.1 R22.2
NetM2_1: M2.1 R23.2 | length 5
  Top Layer w0.3: R23.2 M2.1
NetM3_1: M3.1 R24.2 | length 5
  Top Layer w0.3: M3.1 R24.2
NetM4_1: M4.1 R25.2 | length 5
  Top Layer w0.3: R25.2 M4.1
NetR2_1: R2.1 R4.2 U1.7 | length 4.5
  Top Layer w0.3: R2.1 R4.2 -54.05,16.95 -53.754,17.246 U1.7
NetR4_1: R4.1 R5.2 U1.6 | length 6.9
  Top Layer w0.3: v1(-54.9,20) -55,19.9 R4.1 -54.45,18.05 -54.154,17.754 U1.6 ; v1(-53.1,20) R5.2
  Int2-B w0.3: v1(-54.9,20) v1(-53.1,20)
NetR5_1: R5.1 R6.2 U1.2 | length 7.1
  Top Layer w0.3: R5.1 v1(-50,20) ; U1.2 -49.018,17.246 -48.45,17.814 -48.45,17.85 -48.25,18.05 R6.2 -48,19.8 v1(-48.2,20)
  Int2-B w0.3: v1(-50,20) v1(-48.2,20)
NetR6_1: R6.1 R7.1 U1.1 | length 4.5
  Top Layer w0.3: U1.1 -48.212,16.738 R6.1 R7.1
NetR10_2: R10.2 R11.1 U2.2 | length 9.7
  Top Layer w0.3: R10.2 -51.35,5.3 v2(-50.2,5.3) ; U2.2 -48.946,2.246 -48.75,2.05 -48,2.05 R11.1@-47.9,1.95 ; R11.1@-48,2.15 v1(-48,3.2)
  Int1_T w0.3: v1(-48,3.2) v1@-48,3.295
  Int2-B w0.3: v2(-50.2,5.3) -49.1,5.3 -48.7,4.9 -48.7,4 -48.175,3.475 -48.175,3.47 v1@-48,3.295
NetR11_2: R11.2 R12.1 | length 1.6
  Top Layer w0.3: R12.1 R11.2@-47.9,0.85
NetR12_2: R12.2 R13.1 U2.1 | length 9.5
  Top Layer w0.3: U2.1 -49.138,1.738 -49,1.6 -49,0.9 -48.95,0.95 ; -49,-1.8 -48.95,-1.85 R12.2
  Top Layer w0.7: R13.1 -49.4,-4 -49,-3.6 -49,-1.8 -49,0.9
NetR14_2: R14.2 R15.2 R16.2 U2.3 | length 9.5
  Top Layer w0.3: R14.2 -48.7,4.95 -48.7,4 ; U2.3 -49.146,2.754 -48.7,3.2 -48.7,4 ; R16.2 R15.2 -48.65,3.95 -48.7,4
NetR26_1: R26.1 SW1.2 | length 12.1
  Top Layer w0.3: R26.1 -17.3,34.1 -15.7,32.5 -9.3,32.5 -8.474,33.326 -8.474,34.651 SW1.2
NetR27_1: R27.1 SW1.1 | length 6.2
  Top Layer w0.3: R27.1 -15.7,34.136 -15.264,33.7 -13.5,33.7 -12.525,34.675 SW1.1
NetR30_1: R30.1 SW1.8 TP9.1 | length 11.1
  Top Layer w0.5: 11.237,33.512 11.412,33.512 ; R30.1 12.4,32.35
  Top Layer w0.7: SW1.8 10.075,34.675 11.237,33.512 12.4,32.35 ; 11.412,33.512 TP9.1
NetR31_2: R31.2 R48.2 SW1.7 | length 28.8
  Top Layer w0.3: R48.2 -20.5,36.824 -20.324,37 -19.1,37 ; R31.2 -18.9,36.8 -19.1,37 ; SW1.7 4.25,36.15 2.8,37.6 -18.5,37.6 -19.1,37
NetR32_2: R32.2 SW1.6 | length 10.3
  Top Layer w0.3: SW1.6 1.71,33.19 2.3,32.6 8.4,32.6 9.2,31.8 R32.2
NetR33_2: R33.2 R34.1 | length 3.1
  Top Layer w0.3: R33.2 -30.1,36.824 -29.924,37 -28.726,37 -28.5,36.774 R34.1 R34.1@-28.55,36.2
NetR34_2: R34.2 SW1.5 | length 34.1
  Top Layer w0.3: R34.2 -28.5,33.9 -26.9,32.3 -24.4,29.8 -3,29.8 -0.83,31.97 SW1.5
NetR35_2: R35.2 R36.1 | length 3.1
  Top Layer w0.3: R35.2 -26.9,36.8 -26.7,37 -25.476,37 -25.3,36.824 R36.1
NetR36_2: R36.2 SW1.4 | length 26.8
  Top Layer w0.3: R36.2 -25.3,34.4 -23.7,32.8 -21.6,30.7 -5.5,30.7 -3.37,32.83 SW1.4
NetR37_2: R37.2 R38.1 | length 3.1
  Top Layer w0.3: R37.2 -23.7,36.8 -23.5,37 -22.3,37 -22.1,36.8 R38.1
NetR38_2: R38.2 SW1.3 | length 20.1
  Top Layer w0.3: R38.2 -22.1,34.2 -19.5,31.6 -7.8,31.6 -6.074,33.326 -6.074,34.511 SW1.3
NetU2_6: U2.6 U2.7 | length 0.5
  Top Layer w0.2: U2.7 U2.6
OFFSET_N: J4.2 SW1.16 TP4.1 | length 48.2
  Top Layer w0.15: v2(-1.9,12.8) -1.05,11.95 J4.2
  Top Layer w0.3: TP4.1 v2(-18.3,21) ; v2(-12.8,42.8) -12.719,42.8 -12.594,42.925 SW1.16
  Int2-B w0.3: v2@-18.3,20.976 -17.724,20.4 -14.4,20.4 ; v2(-12.8,42.8) -14.5,41.1 -14.5,20.5 -14.4,20.4 ; v2(-1.9,12.8) -1.957,12.857 -2.157,12.857 -3.2,13.9 -7.5,13.9 -14,20.4 -14.4,20.4
OFFSET_P: J4.6 SW1.15 TP3.1 | length 45.7
  Top Layer w0.15: v2(-0.9,12.7) -0.35,12.15 J4.6
  Top Layer w0.3: TP3.1 -13.303,21 -13.203,20.9 v2(-13.122,20.9) ; v2(-12.961,41.231) -12.93,41.2 -8.8,41.2 -8.45,41.55 SW1.15
  Int2-B w0.3: v2(-12.961,41.231) -12.961,41.15 -13.122,40.989 -13.122,20.422 -7.05,14.35 -2.55,14.35 v2(-0.9,12.7)
OUT_N: FL1.4 J4.5 | length 47.2
  Top Layer w0.15: -0.7,7.3 -0.35,7.65 J4.5
  Top Layer w0.7: FL1.4 -36.8,26 -36.4,25.6 -36.4,25.335 -35.99,24.925 -33.548,24.925 -15.373,6.75 -1.25,6.75 -0.7,7.3
OUT_P: FL1.3 J4.7 | length 48.4
  Top Layer w0.15: 0,6.774 J4.7
  Top Layer w0.7: FL1.3 -36.8,23 -36.4,23.4 -36.4,23.665 -35.99,24.075 -33.9,24.075 -15.725,5.9 -0.874,5.9 0,6.774
OUTF_N: FL1.1 R1.1 | length 3.8
  Top Layer w0.7: R1.1 -42.9,25.3 -42.2,26 FL1.1
OUTF_P: FL1.2 R8.1 | length 3.8
  Top Layer w0.7: R8.1 -42.9,23.7 -42.2,23 FL1.2
PGND: C15.1 F3.4 J4.MP3 J4.MP4 TP11.1 | length 51.1
  Top Layer w0.3: 3.35,9.95 3.283,10.017 J4.MP3 J4.MP4 3.333,10.983 3.35,11
  Top Layer w0.5: -3.7,18.4 -3.8,18.3 ; 17.2,32.5 17.3,32.6 F3.4@20,32.6 ; -3.8,18.3 -3.9,18.4 -4.7,18.4 C15.1 -4.695,17.455 -4.093,17.455 -3.8,17.748 -3.8,18.3
  Top Layer w0.7: -3.8,17.748 -1.852,15.8 0.7,15.8 1.95,14.55 3.35,14.55 3.35,11 3.35,10.084 3.283,10.017 ; -3.7,18.4 -2.65,19.45 -2.65,20.648 0.302,23.6 10,23.6 ; TP11.1 10,23.6 ; 17.1,27.2 12.2,27.2 10,25 10,23.6
TEMP_OK: D1.1 J4.12 TP1.1 | length 81.2
  Top Layer w0.15: J4.12 0.715,11.465 0.715,12.415 1.4,13.1 v2(1.4,13.2)
  Top Layer w0.3: D1.1 -62,36.2 -54.3,28.5 -32.9,28.5 -23,18.6 -7.4,18.6 v2(-6.2,19.8) TP1.1 TP1.1@-4.725,21.275
  Int2-B w0.3: v2(-6.2,19.8) -0.7,14.3 -0.7,13.6 -0.3,13.2 v2(1.4,13.2)
TEMP_OUT: IC1.9 IC1.13 J4.14 TP2.1 | length 81
  Top Layer w0.15: J4.14 1.05,11.95 1.4,12.3 v2(2,12.3)
  Top Layer w0.2: v1(-50.6,37) -50.6,36.9 -50.25,36.55 IC1.9 ; v1(-48.8,32.6) -48.55,32.85 IC1.13
  Top Layer w0.3: v1(-41.3,30) -32.7,30 -26,23.3 -4.1,23.3 -1.7,25.7 1.95,25.7 v2(2.002,25.752) ; TP2.1 v2(1.9,21)
  Int1_T w0.3: v1(-50.6,37) -48.8,35.2 v1(-48.8,32.6) -46.2,30 v1(-41.3,30)
  Int2-B w0.3: v2(2,12.3) 2,20.819 1.9,20.919 1.9,25.569 2.002,25.671 v2(2.002,25.752)
TEMP_REF: IC1.4 J4.10 SW1.10 SW1.11 SW1.12 SW1.13 SW1.14 TP12.1 | length 115.3
  Top Layer w0.15: J4.10 0.35,12.85 0.9,13.4 v2(0.9,14)
  Top Layer w0.25: IC1.4 IC1.4@-45.96,36.55
  Top Layer w0.3: IC1.4@-45.96,36.55 -45.95,36.56 -45.95,38.986 -45.236,39.7 -37.9,39.7 -36.1,41.5 -30.3,41.5 -29.3,40.5 v2(-10,40.5) -5.9,40.5 ; SW1.14 -5.91,40.51 -5.9,40.5 ; SW1.13@-3.34,43 -3.34,40.54 -3.3,40.5 ; SW1.12@-0.8,42.895 -0.8,40.5 ; SW1.11@1.74,43 1.74,40.5 ; SW1.10 4.25,40.95 3.8,40.5 1.74,40.5 ; -5.9,40.5 -3.3,40.5 ; -3.3,40.5 -0.8,40.5 ; -0.8,40.5 v2(1.2,40.5) 1.74,40.5
  Top Layer w0.5: TP12.1 v2(-10,22.6) ; SW1.12 SW1.12@-0.8,42.895
  Int2-B w0.3: v2(-10,22.6) v2(-10,40.5) ; v2(0.9,14) 1.178,14.278 1.178,40.478 v2(1.2,40.5)
V_amp: C11.2 C12.2 F3.1 R21.2 R28.2 TP8.1 U4.2 | length 41.3
  Top Layer w0.5: TP8.1 R21.2 17.4,21.05 v2(17.4,21.9) v2(17.4,22.8) ; v2(15.799,40.001) v2(16.7,40.001) v2(17.5,40.001) ; R28.2 23.35,42.25 U4.2
  Top Layer w1: v2(17.5,40.001) 24.001,40.001 U4.2 ; v2(29.8,28.4) v2(30.7,28.4) v2(32,28.4)
  Int1_T w0.5: v2(15.799,40.001) v2(16.7,40.001) ; v2(17.4,21.9) v2(17.4,22.8) 16.7,23.5 v2(16.7,40.001) ; v2(17.5,40.001) v2(16.7,40.001)
  other v2: 24.2,39 25.2,39 26.2,39 27.2,39 24.2,40 25.2,40 26.2,40 27.2,40 24.2,41 25.2,41 26.2,41 27.2,41 24.2,42 25.2,42 26.2,42 27.2,42
V_cooler: C15.2 J4.MP1 J4.MP2 R30.2 TP10.1 | length 47.1
  Top Layer w0.3: -3.353,10.017 J4.MP1 J4.MP2 -3.267,10.983 -3.35,10.9
  Top Layer w0.5: -5.6,15.4 -5.5,15.3 -4.993,15.3 -4.7,15.593 C15.2 -5.55,16.35 -5.6,16.4 ; 12.395,28.795 12.395,29.945 R30.2
  Top Layer w0.7: -3.353,10.017 -3.353,10.371 ccw(c-6.5,10.5) -3.353,10.629 -3.353,12.553 -5.6,14.8 -5.6,15.4 -5.6,16.4 -5.6,18.7 -5.1,19.2 -4.3,19.2 -3.5,20 -3.5,21 0,24.5 v2(2.9,24.5) v2(3.6,24.5) 8.2,24.5 12.395,28.695 12.395,28.795 ; v2(2.9,21) v2(3.6,21) TP10.1
  Int1_T w0.7: v2(2.9,21) v2(3.6,21) ; v2(2.9,24.5) v2(3.6,24.5)
  Int2-B w0.7: v2(2.9,24.5) v2(3.6,24.5) v2(3.6,21)
VCC: J4.8 R26.2 | length 35.9
  Top Layer w0.15: J4.8@0,11.407 J4.8 v2(0,14)
  Top Layer w0.3: R26.2 -16.676,36.15 -16.5,35.974 -16.5,34.3 -15.4,33.2 -9.449,33.2 v2(-9.4,33.249)
  Int2-B w0.3: v2(-9.4,33.249) -9.073,32.922 -9.073,24.3 0.025,15.202 0.025,14.025 v2(0,14)
VCC_F: J4.4
Vin: D3.1 F2.2 L1.1 L2.1 TP5.1 | length 29.3
  Top Layer w0.3: D3.1 v2(46.45,28.5)
  Top Layer w0.7: TP5.1 v2(40.1,34.5) v2(40.8,34.5)
  Top Layer w1: L1.1@46.49,38.5 L2.1@46.49,42.5 ; L1.1 46.742,38.242 v2(46.742,36.425) 46.767,36.4 F2.2
  Int1_T w0.3: v2(46.45,28.5) 46.45,36.099 46.725,36.374 46.725,36.425 v2(46.742,36.425)
  Int1_T w0.7: v2(40.1,34.5) v2(40.8,34.5) 41.9,34.5 43.825,36.425 46.45,36.425 v2@46.725,36.425 ; v2(46.742,36.425) v2(47.375,36.425)
pads on no net: IC1.3 IC1.10 J5.MH1 J5.MH2 J5.MH3 M5.1 M6.1

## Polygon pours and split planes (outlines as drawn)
GND on Int1_T "GND" (solid, pour order 16): -71.8,45 -71.8,-19 72.2,-19 72.2,45
V_amp on Int1_T "GND" (solid, pour order 14): 23.2,43 28.2,43 29.2,42 29.2,31 30.2,30 34.2,30 34.2,26 26.2,26 22.2,30 22.2,31 22.2,42
GND on Int1_T "GND" (solid, pour order 10): -0.7,10.5 0.7,10.5 1.2,10 1.2,7.5 0.7,7 0.3,7 -1.7,5 -5,5 -16.6,5 -18.6,7 -32.9,21.3 -38.2,21.3 -63.3,21.3 -63.5,21.3 -63.5,27.8 -33.5,27.8 -30.5,24.8 -13.3,7.6 -4.6,7.6 -3.1,7.6 -2.4,8.3 -0.7,10
NetD2_1 on Int1_T "GND" (solid, pour order 0): 65.2,-13 55.2,-13 55.2,42 56.2,43 57.2,44 63.2,44 65.2,44 66.2,43 66.2,42 66.2,-12
no net on Bottom Overlay "RADIATOR_2" (solid): -42.5,19 42.5,19 42.5,-19 -42.5,-19
GND on Top Layer "GND" (solid, remove dead copper, pour order 20): -71.8,-19 -71.8,45 72,45 72,-18.8 72.2,-19
GND on Top Layer "GND" (solid, pour order 2): 29.7,39.5 40.2,39.5 40.2,36.5 36.7,36.5 36.7,30 29.7,30
GND on Top Layer "GND" (solid, pour order 4): 44.2,33.5 44.2,36 51.7,36 51.7,38.5 49.2,38.5 48.7,39 48.7,39.5 48.7,43.5 49.7,44.5 50.7,44.5 59.2,44.5 59.7,44 59.7,41.5 59.7,24 53.7,24 52.7,25 51.7,26 51.7,30 48.2,33.5 46.7,33.5
PGND on Top Layer "GND" (solid, pour order 8): 16.2,33.5 16.2,35.5 16.7,36 28.2,36 28.7,35.5 28.7,34.5 28.7,24.5 28.2,24 16.7,24 16.2,24.5
GND on Bottom (GND) "GND" (solid, pour order 6): -71.8,-19 -71.8,45 72,45 72,-18.8 72.2,-19
GND on Int2-B "GND" (solid, pour order 18): -71.8,45 -71.8,-19 72.2,-19 72.2,45
3V3 on Int2-B "GND" (solid, pour order 12): -56.8,-6 -42.8,-6 -41.85,-5.05 -41.85,23.45 -29.8,35.5 -29.8,38 -29.8,44 -56.8,44 -57.8,43 -57.8,-4 -57.8,-5

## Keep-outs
Top Layer:
  region: -1.9,11 -2,11.1 -2,11.5 -2.769,11.5 -2.792,11.477 -2.8,11.9 -1.397,11.9 -1.34,11.843 -1.34,11.05 1.34,11.05 1.34,11.843 2.457,11.843 2.5,11.8 2.5,11.4 1.955,11.4 1.93,11.375 1.93,9.625 2.7,9.624 2.7,9.1 1.388,9.1 1.34,9.148 1.34,9.95 -1.34,9.95 -1.34,9.197 -2.097,9.197 -2.73,9.203 -2.73,9.624 -1.93,9.625 -1.93,10.87 -1.9,10.9

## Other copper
Top Layer:
  rectangle net PGND: 16.2,26 18.2,33.5

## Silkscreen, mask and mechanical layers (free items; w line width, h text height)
Top Overlay:
  drawing of 17 lines, arcs and shapes, not listed
  text "REF" at -42.5,40.4 h1 r45
  text "WD+" at -55.2,39.2 h1 r45
  text "T_OK" at -61.5,34.3 h1 r90.05
  text "V_IN" at 35.4,34.2 h1 r45
  text "2A/16V" at 65.2,34 h1
  text "WD_OK" at -59.4,33.3 h1 r90.05
  text "WD_OUT" at -38.1,32.7 h1 r45
  text "V_c1R" at 13.9,32.7 h1 r45
  text "WD-" at -55.1,31.8 h1 r45
  text "DIFF" at -61.8,28 h1 r0.05
  text "SUPPLY" at 37.4,28 h1 r0.05
  text "OF_N" at -10.3,27.651 h1.5 r90.05
  text "OF_P" at -7.7,27.651 h1.5 r90.05
  text "253K" at -5,27.652 h1.5 r90.05
  text "263K" at -2.5,27.652 h1.5 r90.05
  text "273K" at 0,27.652 h1.5 r90.05
  text "283K" at 2.5,27.652 h1.5 r90.05
  text "293K" at 5.022,27.652 h1.5 r90.05
  text "N" at -57.2,25.305 h1 r0.05
  text "TEC_ON" at 7.6,24.652 h1.5 r90.05
  text "P" at -57.2,22.4 h1 r0.05
  text "T_REF" at -8.9,22 h1 r45
  text "T_OK" at -4.061,22 h1 r45
  text "T_OUT" at 1.5,22 h1 r45
  text "V_cool" at 6.5,22 h1 r45
  text "PGND" at 11.5,22 h1 r45
  text "V_amp" at 16.4,22 h1 r45
  text "3.3V" at 56.7,21 h1 r45
  text "Offset / N" at -17.6,20.7 h1 r45
  text "Offset / P" at -12.5,20.7 h1 r45
  text "GND_IN" at 54.8,14.3 h1 r45
  text "DIFF" at -61.8,14 h1 r0.05
  text "AMP" at -61.8,12 h1 r0.05
  text "GND" at 56.9,11.7 h1 r0.05
  text "N" at -57.2,9.645 h1 r0.05
  text "+5V" at 57,9.2 h1 r0.05
  text "P" at -57.2,6.74 h1 r0.05
  text "GND" at 57,6.6 h1 r0.05
  text "SINGLE" at -61.8,-3 h1 r0.05
  text "AM Evaluation board / 247-722-03" at -63.98,-13.908 h1 r0.05
  text "5V/1A" at 61.6,-14.6 h1 r0.05
Bottom Overlay:
  drawing of 29 lines, arcs and shapes, not listed
  text "AM Evaluation board / 247-722-03" at 17.5,20.085 h1.5 r359.95
Mechanical 1:
  the board outline again, w0.1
